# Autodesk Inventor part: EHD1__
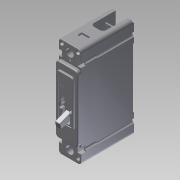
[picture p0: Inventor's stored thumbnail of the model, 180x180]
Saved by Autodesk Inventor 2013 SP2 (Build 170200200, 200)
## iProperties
Created: 2014-08
Part Number: EHD1__
Material: Generic
Document SubType Name: Modeling
Designer: DM/JS
Density: 1 g/cm^3
Description: TYPE EHD THERMAL MAGNETIC CIRCUIT BREAKERS SINGLE POLE, SERIES C
Translation Standard: STEP AP214IS
FileName: Y:\ECO-062745\WIP\New\FD1_.stp
PreProcessor: Autodesk Inventor 2012
PostProcessor: Build: 219, Release: 2012 SP2 - Date: Fri 04/27/2012
Sent Units: inch
Uncertainty: 0.00039370078740199997
MXEDIT: false
MXINVTNRV: INV Versioned Component|EHD1_|003.0
Author: DM/JS
Revision Number: 003
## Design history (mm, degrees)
node "EHD1_"
node "L1"
node "T1"
body "Solid1"
node "Base1"
